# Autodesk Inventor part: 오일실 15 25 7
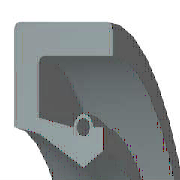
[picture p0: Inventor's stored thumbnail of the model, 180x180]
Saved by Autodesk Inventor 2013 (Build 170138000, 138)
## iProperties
Created: 2012-02
Part Number: 오일실 15 25 7
Material: 고무
Description: 오일 실 - 스프링 장착, 금속 케이스 SM
Document SubType Name: Modeling
Standard: JIS B 2402
Designer: mdu-01
Standards Organization: JIS
Language: ko-KR
Size Designation: 15 25 7 A
Categories: <MemberInstance><Categories><Category DisplayName="샤프트 부품" InternalName="7f7aeb1f-a693-4053-b835-cee3144e0d98" Mnemonic="SHFT"><Category DisplayName="실링" Intern
Density: 0.93 g/cm^3
IsCustomPart: 1
Author: mdu-01
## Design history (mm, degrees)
body "Solid1"
revolve "회전1" stored, may be unused: angle "d33" = 360 deg
fillet "모깎기1" dims "d34" = 0.35 (= 0.05 x b)
chamfer "모따기1" distance "d35" = 0.7 (= 0.1 x b); stored, may be unused: second distance "d36" = 0.35 (= 0.05 x b), angle "d41" = 45 deg
sketch "스케치2"
  geometry: L1 (8.714, -5.158)-(9.184, -7); L2 (8.214, -4.55)-(8.714, -5.158); L3 (7.5, -1.75)-(8.214, -4.55); L4 (8.167, -0.875)-(7.5, -1.75); L5 (9.284, -0.875)-(8.167, -0.875); L6 (9.284, -1.575)-(9.284, -0.875); L7 (9.284, -5.25)-(9.284, -2.975); L8 (10.5, -5.25)-(9.284, -5.25); L9 (11.5, -1.75)-(10.5, -5.25); L10 (11.5, 0)-(11.5, -1.75); L11 (12.5, 0)-(11.5, 0); L12 (12.5, -7)-(12.5, 0); L13 (9.184, -7)-(12.5, -7); L14 (0, -9.6)-(0, 1.6) reference; L15 (28, 0)-(14, 0) reference; A1 r 0.7 centre (9.284, -2.275) between (9.284, -2.975) and (9.284, -1.575)
  constraints: 26 end point, 4 horizontal, 4 vertical, 2 point on circle, 1 centre point, 1 collinear, 1 parallel
  dimensions: "d2" = 7 distance of L12.start L11.start (= b); "d4" = 0.875 vertical distance of L10.start L5.start (= 0.125 x b); "d6" = 1 distance of L11.start L10.start (= 0.1 x dd - 0.1 x Diam); "d8" = 1.75 distance of L10.start L9.start (= 0.25 x b); "d10" = 1.75 vertical distance of L8.start L1.end (= 0.25 x b); "d12" = 1 horizontal distance of L9.start L8.start (= 0.1 x dd - 0.1 x Diam); "d14" = 0.7 radius of A1 (= 0.1 x b); "d16" = 0 horizontal distance of A1.centre L7.end; "d18" = 0.7 distance of L6.start L5.start (= 0.1 x b); "d20" = 0.66667 horizontal distance of L4.start L3.start (= 0.0666667 x dd - 0.0666667 x Diam); "d22" = 0.1 horizontal distance of L7.start L1.end (= 0.01 x dd - 0.01 x Diam); "d24" = 0.875 vertical distance of L4.start L3.start (= 0.125 x b); "d26" = 2.8 vertical distance of L3.start L2.start (= 0.4 x b); "d28" = 0.71429 horizontal distance of L3.start L2.start (= 0.0714286 x dd - 0.0714286 x Diam); "d30" = 1.84211 vertical distance of L1.start L1.end (= 0.263158 x b); "d32" = 0.5 horizontal distance of L2.start L1.start (= 0.05 x dd - 0.05 x Diam); "d37" = 0 distance between parallel lines of L15 L11; "d38" = 12.5 distance between parallel lines of L14 L12 (= 0.5 x dd); "d39" = 7.5 distance from line of L14 L3.start (= 0.5 x Diam)
other parameters: "dd" = 25 [user parameter; used in 7 equation terms], "Diam" = 15 [user parameter; used in 7 equation terms], "b" = 7 [user parameter; used in 12 equation terms], "d1" = 8 (derived), "d3" = 1 (derived), "d5" = 2 (derived), "d7" = 2 (derived), "d9" = 2 (derived), "d11" = 2 (derived), "d13" = 0.8 (derived), "d15" = 0 (derived), "d17" = 0.8 (derived), "d19" = 1.33333 (derived), "d21" = 0.2 (derived), "d23" = 1 (derived), "d25" = 3.2 (derived), "d27" = 1.42857 (derived), "d29" = 2.10526 (derived), "d31" = 1 (derived), "d40" = 0
